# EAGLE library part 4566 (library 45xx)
Industrial TIME BASE GENERATOR
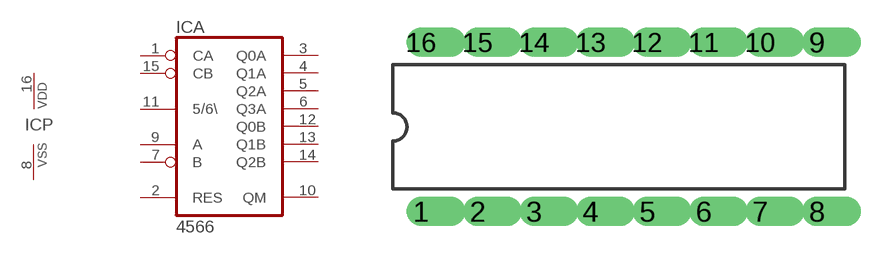
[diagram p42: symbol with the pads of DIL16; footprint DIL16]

Designator prefix IC; gates A=4566 P=PWRN

## 4566N  [DIL16]
1  A:CA  in
2  A:RES  in
3  A:Q0A  out
4  A:Q1A  out
5  A:Q2A  out
6  A:Q3A  out
7  A:B  in
8  P:VSS  pwr
9  A:A  in
10  A:QM  out
11  A:5/6\  in
12  A:Q0B  out
13  A:Q1B  out
14  A:Q2B  out
15  A:CB  in
16  P:VDD  pwr

## Footprint DIL16 (pad centres in mm)
Dual In Line
drill 0.813 offset: 1 -8.89,-3.81; 2 -6.35,-3.81; 3 -3.81,-3.81; 4 -1.27,-3.81; 5 1.27,-3.81; 6 3.81,-3.81; 7 6.35,-3.81; 8 8.89,-3.81; 9 8.89,3.81; 10 6.35,3.81; 11 3.81,3.81; 12 1.27,3.81; 13 -1.27,3.81; 14 -3.81,3.81; 15 -6.35,3.81; 16 -8.89,3.81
